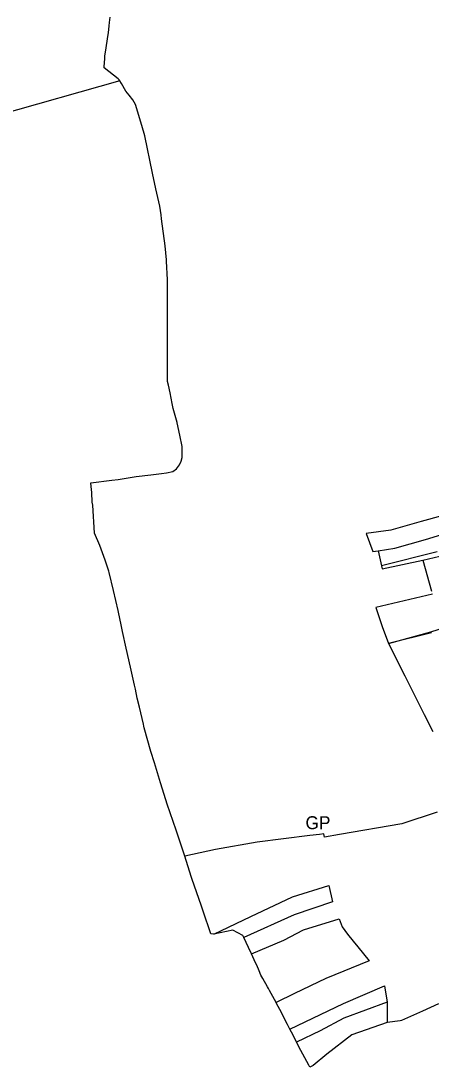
# Model space of a CAD drawing. Extents: x -534397 to -527742, y -1181460 to -1175250.
# Drawn here: x -532132 to -531859, y -1178882 to -1178187 of the extents above; entities that cross this region are included whole.
import ezdxf

# ---------------------------------------------------------------- set-up
doc = ezdxf.new("R2010")
doc.units = 0
for name, color, linetype in [('Hranice obcí', 7, 'Continuous'), ('Hranice parcel', 7, 'Continuous'), ('Hranice státní', 7, 'Continuous')]:
    doc.layers.add(name, color=color, linetype=linetype)

msp = doc.modelspace()

# ---------------------------------------------------------------- linework, layer by layer
at = {"layer": 'Hranice obcí'}
for p, q in [((-531862.54, -1178531.62), (-531843.11, -1178525.5)), ((-531882.98, -1178537.25), (-531862.54, -1178531.62)), ((-531894.2, -1178539.02), (-531882.98, -1178537.25)), ((-531854.83, -1178539.76), (-531891.91, -1178549.13)), ((-531864.47, -1178545.26), (-531852.95, -1178542.5)), ((-531859.14, -1178593), (-531809.44, -1178577.21)), ((-531887.14, -1178600.73), (-531859.14, -1178593)), ((-531858.55, -1178593.69), (-531887.14, -1178600.73)), ((-531951.15, -1178769.16), (-531927, -1178761.58)), ((-531927, -1178761.58), (-531924.4, -1178772.59)), ((-531978.75, -1178782.18), (-531951.15, -1178769.16)), ((-531924.4, -1178772.59), (-531950.05, -1178781.02)), ((-532003.5, -1178794.02), (-531978.75, -1178782.18)), ((-531950.05, -1178781.02), (-531983.53, -1178796.12)), ((-531943.7, -1178791.21), (-531920.06, -1178783.82)), ((-531920.06, -1178783.82), (-531918.16, -1178789.02)), ((-531956.93, -1178798), (-531943.7, -1178791.21)), ((-531918.16, -1178789.02), (-531914.51, -1178794.02)), ((-531978.42, -1178807.02), (-531956.93, -1178798)), ((-531914.51, -1178794.02), (-531910.69, -1178798.66)), ((-531910.69, -1178798.66), (-531907.57, -1178802.45)), ((-531907.57, -1178802.45), (-531900.05, -1178811.64)), ((-531900.05, -1178811.64), (-531928.87, -1178823.54)), ((-531928.87, -1178823.54), (-531949.87, -1178833.46)), ((-531917.06, -1178840.14), (-531889.8, -1178828.32)), ((-531889.8, -1178828.32), (-531888.11, -1178839.22)), ((-531949.87, -1178833.46), (-531962.08, -1178839.48)), ((-531952.78, -1178857.21), (-531917.06, -1178840.14)), ((-531888.11, -1178839.22), (-531916.87, -1178849.85)), ((-531888.11, -1178839.22), (-531888.07, -1178852.67)), ((-531916.87, -1178849.85), (-531932.73, -1178858.33)), ((-531932.73, -1178858.33), (-531948.43, -1178865.81))]:
    msp.add_line(p, q, dxfattribs=at)
at = {"layer": 'Hranice parcel'}
for p, q in [((-532073.03, -1178189.79), (-532072.82, -1178187.71)), ((-532072.82, -1178187.71), (-532072.55, -1178184.24)), ((-532073.69, -1178195.61), (-532073.51, -1178194.51)), ((-532073.51, -1178194.51), (-532073.03, -1178189.79)), ((-532075.57, -1178207.36), (-532073.69, -1178195.61)), ((-532075.98, -1178209.91), (-532075.57, -1178207.36)), ((-532076.42, -1178217.1), (-532076.09, -1178211.73)), ((-532076.09, -1178211.73), (-532075.98, -1178209.91)), ((-532076.47, -1178217.89), (-532076.42, -1178217.1)), ((-532067.17, -1178225.25), (-532076.47, -1178217.89)), ((-532066.56, -1178225.92), (-532067.17, -1178225.25)), ((-532066, -1178226.53), (-532066.56, -1178225.92)), ((-532064.99, -1178228.28), (-532066, -1178226.53)), ((-532062.02, -1178233.44), (-532064.99, -1178228.28)), ((-532059.9, -1178236.06), (-532062.02, -1178233.44)), ((-532057.45, -1178239.08), (-532059.9, -1178236.06)), ((-532055.53, -1178242.17), (-532057.45, -1178239.08)), ((-532051.97, -1178254), (-532055.53, -1178242.17)), ((-532049.78, -1178261.4), (-532051.97, -1178254)), ((-532049.45, -1178262.97), (-532049.78, -1178261.4)), ((-532044.2, -1178287.89), (-532049.45, -1178262.97)), ((-532042, -1178298.36), (-532044.2, -1178287.89)), ((-532039.33, -1178309.8), (-532042, -1178298.36)), ((-532038.59, -1178315.5), (-532039.33, -1178309.8)), ((-532038.23, -1178318.27), (-532038.59, -1178315.5)), ((-532035.91, -1178336.18), (-532038.23, -1178318.27)), ((-532035, -1178345.57), (-532035.91, -1178336.18)), ((-532034.95, -1178346.51), (-532035, -1178345.57)), ((-532034.36, -1178358.76), (-532034.95, -1178346.51)), ((-532034.24, -1178361.28), (-532034.36, -1178358.76)), ((-532034.24, -1178364.83), (-532034.24, -1178361.28)), ((-532034.23, -1178372.46), (-532034.24, -1178364.83)), ((-532034.22, -1178385.1), (-532034.23, -1178372.46)), ((-532034.21, -1178398.43), (-532034.22, -1178385.1)), ((-532034.2, -1178406.71), (-532034.21, -1178398.43)), ((-532034.19, -1178417.03), (-532034.2, -1178406.71)), ((-532034.18, -1178423.39), (-532034.19, -1178417.03)), ((-532034.18, -1178426.33), (-532034.18, -1178423.39)), ((-532033.65, -1178428.87), (-532034.18, -1178426.33)), ((-532032.6, -1178433.89), (-532033.65, -1178428.87)), ((-532031.11, -1178441.07), (-532032.6, -1178433.89)), ((-532030.43, -1178444.35), (-532031.11, -1178441.07)), ((-532027.83, -1178453.71), (-532030.43, -1178444.35)), ((-532027.75, -1178454.02), (-532027.83, -1178453.71)), ((-532026.08, -1178462.12), (-532027.75, -1178454.02)), ((-532024.5, -1178469.77), (-532026.08, -1178462.12)), ((-532024.51, -1178477.08), (-532024.5, -1178470.8)), ((-532024.5, -1178470.8), (-532024.5, -1178469.77)), ((-532026.27, -1178481.87), (-532025.24, -1178479.37)), ((-532025.24, -1178479.37), (-532024.51, -1178477.08)), ((-532045.37, -1178488.46), (-532038.32, -1178487.59)), ((-532038.32, -1178487.59), (-532034.97, -1178487.17)), ((-532034.97, -1178487.17), (-532030.85, -1178486.22)), ((-532030.85, -1178486.22), (-532028.26, -1178484.49)), ((-532028.26, -1178484.49), (-532026.27, -1178481.87)), ((-532085.28, -1178493.93), (-532071.33, -1178492.13)), ((-532085.01, -1178496.25), (-532085.28, -1178493.93)), ((-532071.33, -1178492.13), (-532067.08, -1178491.58)), ((-532067.08, -1178491.58), (-532055.08, -1178489.62)), ((-532055.08, -1178489.62), (-532045.37, -1178488.46)), ((-532084.55, -1178500.22), (-532085.01, -1178496.25)), ((-532084.41, -1178506.71), (-532084.55, -1178500.22)), ((-532084.08, -1178508.67), (-532084.41, -1178506.71)), ((-532082.88, -1178527.22), (-532084.08, -1178508.67)), ((-532079.34, -1178535.51), (-532082.88, -1178527.22)), ((-532075.84, -1178545.32), (-532079.34, -1178535.51)), ((-532073.33, -1178552.54), (-532075.84, -1178545.32)), ((-532073.02, -1178553.43), (-532073.33, -1178552.54)), ((-532070.25, -1178565.49), (-532073.02, -1178553.43)), ((-532067.18, -1178578.67), (-532070.25, -1178565.49)), ((-532066.94, -1178579.81), (-532067.18, -1178578.67)), ((-532065.16, -1178588.3), (-532066.94, -1178579.81)), ((-532064.21, -1178592.66), (-532065.16, -1178588.3)), ((-532061.8, -1178603.78), (-532064.21, -1178592.66)), ((-532061.78, -1178603.89), (-532061.8, -1178603.78)), ((-532060.01, -1178611.44), (-532061.78, -1178603.89)), ((-532058.46, -1178618.44), (-532060.01, -1178611.44)), ((-532056.26, -1178628.38), (-532058.46, -1178618.44)), ((-532055.66, -1178631.14), (-532056.26, -1178628.38)), ((-532054.38, -1178637.05), (-532055.66, -1178631.14)), ((-532052.95, -1178643.13), (-532054.38, -1178637.05)), ((-532050.34, -1178654.27), (-532052.95, -1178643.13)), ((-532050.02, -1178655.63), (-532050.34, -1178654.27)), ((-532049.77, -1178656.68), (-532050.02, -1178655.63)), ((-532045.33, -1178672.4), (-532049.77, -1178656.68)), ((-532042.96, -1178680.13), (-532045.33, -1178672.4)), ((-532038.88, -1178693.42), (-532042.96, -1178680.13)), ((-532035.38, -1178704.6), (-532038.88, -1178693.42)), ((-532034.49, -1178707.44), (-532035.38, -1178704.6)), ((-532028.42, -1178724.91), (-532034.49, -1178707.44)), ((-532027.15, -1178728.83), (-532028.42, -1178724.91)), ((-532022.86, -1178742.1), (-532027.15, -1178728.83)), ((-532018.48, -1178755.63), (-532022.86, -1178742.1)), ((-532018.03, -1178756.92), (-532018.48, -1178755.63)), ((-532011.6, -1178775.36), (-532018.03, -1178756.92)), ((-532010.46, -1178778.65), (-532011.6, -1178775.36)), ((-532005.42, -1178793.83), (-532010.46, -1178778.65)), ((-531990.72, -1178791.42), (-532003.5, -1178794.02)), ((-531984.1, -1178794.92), (-531990.72, -1178791.42)), ((-532003.5, -1178794.02), (-532005.42, -1178793.83)), ((-531983.53, -1178796.12), (-531984.1, -1178794.92)), ((-531980.32, -1178802.87), (-531983.53, -1178796.12)), ((-531978.42, -1178807.02), (-531980.32, -1178802.87)), ((-531975.69, -1178812.96), (-531978.42, -1178807.02)), ((-531974.89, -1178814.71), (-531975.69, -1178812.96)), ((-531973.33, -1178818.34), (-531974.89, -1178814.71)), ((-531972.07, -1178821.29), (-531973.33, -1178818.34)), ((-531971.47, -1178822.37), (-531972.07, -1178821.29)), ((-531970.9, -1178823.4), (-531971.47, -1178822.37)), ((-531967.78, -1178829.07), (-531970.9, -1178823.4)), ((-531967.16, -1178830.2), (-531967.78, -1178829.07)), ((-531966.51, -1178831.39), (-531967.16, -1178830.2)), ((-531962.08, -1178839.48), (-531966.51, -1178831.39)), ((-531961.47, -1178840.6), (-531962.08, -1178839.48)), ((-531958.74, -1178845.59), (-531961.47, -1178840.6)), ((-531853.87, -1178840.29), (-531864.5, -1178845.09)), ((-531957.67, -1178847.67), (-531958.74, -1178845.59)), ((-531954.41, -1178853.99), (-531957.67, -1178847.67)), ((-531864.5, -1178845.09), (-531878.54, -1178851.32)), ((-531952.78, -1178857.21), (-531954.41, -1178853.99)), ((-531888.07, -1178852.67), (-531911.51, -1178860.91)), ((-531879.46, -1178851.73), (-531888.07, -1178852.67)), ((-531878.54, -1178851.32), (-531879.46, -1178851.73)), ((-531950.75, -1178861.23), (-531952.78, -1178857.21)), ((-531948.43, -1178865.81), (-531950.75, -1178861.23)), ((-531911.51, -1178860.91), (-531928.32, -1178873.76)), ((-531945.64, -1178871.34), (-531948.43, -1178865.81)), ((-531940.19, -1178881.19), (-531945.64, -1178871.34)), ((-531928.32, -1178873.76), (-531937.28, -1178881.25)), ((-531939.53, -1178882.38), (-531940.19, -1178881.19)), ((-531937.28, -1178881.25), (-531939.53, -1178882.38))]:
    msp.add_line(p, q, dxfattribs=at)
for points in [[(-531851.65, -1178515.86), (-531865.4, -1178519.58), (-531885.59, -1178525.38), (-531902.08, -1178527.59), (-531897.65, -1178539.5), (-531894.2, -1178539.02), (-531891.91, -1178549.13), (-531891.48, -1178551.02), (-531864.47, -1178545.26), (-531858.6, -1178565.89)], [(-531858.04, -1178567.84), (-531895.66, -1178576.72), (-531891.4, -1178589.29), (-531887.14, -1178600.73), (-531876.32, -1178622.22), (-531863.45, -1178647.79), (-531857.73, -1178659.16)], [(-531854.72, -1178712.96), (-531878.27, -1178720.57), (-531919.92, -1178727.73), (-531929.79, -1178729.43), (-531930.31, -1178727.28), (-531933.07, -1178727.62), (-531939.64, -1178728.43), (-531974.53, -1178732.73), (-532002.34, -1178737.57), (-532022.86, -1178742.1)]]:
    msp.add_lwpolyline(points, dxfattribs=at)
at = {"layer": 'Hranice státní'}
msp.add_line((-532066, -1178226.53), (-533270.78, -1178567.7), dxfattribs=at)

# ---------------------------------------------------------------- texts
at = {"layer": 'Hranice parcel'}
msp.add_text('GP', height=8.59, dxfattribs=at).set_placement((-531942.45, -1178724.16))

doc.saveas('drawing.dxf')
